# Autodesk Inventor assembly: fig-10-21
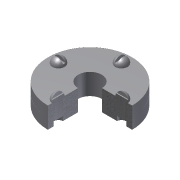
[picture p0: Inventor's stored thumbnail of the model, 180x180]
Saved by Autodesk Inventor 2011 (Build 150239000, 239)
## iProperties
Shininess: 64.0
Angle Display Precision: 2
Document Length Units: 11269
Document Angle Units: 11279
Document Time Units: 11290
Document Mass Units: 11283
Document Length Units Precision: 3
Document Angle Units Precision: 2
Created: 2002-02
Part Number: fig-10-21
Document SubType Name: Assembly
Designer: ***
Density: 0.0
Volumn: 0.0
Area: 0.0
PropertySet Name: Model Information
Control State: 0
Master: False
Checked Out: False
Author: ***
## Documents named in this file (3)
- C:\Users\CADSoft\Desktop\part files\c10-inv-2011-prt\fig-10-21.iam
- C:\Users\CADSoft\Desktop\inventor\c10-inv-2010-prt\c10\Screw.ipt
- C:\Users\CADSoft\Desktop\inventor\c10-inv-2010-prt\c10\test.ipt
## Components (6 placed, 2 different names)
1. test:1 — Insert:1, Insert:2
2. test:2 — Insert:1
3. Screw:1 — Angle:1, Insert:2
4. Screw:11
5. Screw:12
6. Screw:13
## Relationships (3: Insert 2, Angle 1)
- Insert:1: test:1 ↔ test:2
- Angle:1: Screw:1
- Insert:2: test:1 ↔ Screw:1
